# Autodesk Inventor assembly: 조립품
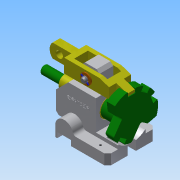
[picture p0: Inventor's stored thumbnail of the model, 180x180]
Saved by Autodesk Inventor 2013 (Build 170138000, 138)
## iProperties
Created: 2016-11
Part Number: 조립품
Document SubType Name: Assembly
Designer: Administrator
Author: Administrator
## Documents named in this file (8)
- C:\Users\Administrator\Desktop\461107V1024\조립품.iam
- C:\Users\Administrator\Desktop\461107V1024\본체.ipt
- C:\Users\Administrator\Desktop\461107V1024\부시.ipt
- C:\Users\Administrator\Desktop\461107V1024\분할대.ipt
- C:\Users\Administrator\Desktop\461107V1024\분할축.ipt
- C:\Users\Administrator\Desktop\461107V1024\와셔.ipt
- C:\Users\Administrator\Desktop\461107V1024\원통형핀.ipt
- C:\Users\Administrator\Desktop\461107V1024\클레비스핀.ipt
